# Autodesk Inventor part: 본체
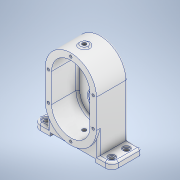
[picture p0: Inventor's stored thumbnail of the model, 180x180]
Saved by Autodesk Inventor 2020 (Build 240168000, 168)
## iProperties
Created: 2021-05
Part Number: 본체
Material: 알루미늄 6061
Document SubType Name: Modeling
Designer: Owner
Density: 2.7 g/cm^3
Appearance: 알루미늄 - 평지
Mass: 752.167 g
Surface Area: 589.363 cm^2
Volume: 278.58 cm^3
Author: Owner
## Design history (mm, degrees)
sketch "스케치2"
  geometry: L1 (0, 17.5)-(0, -17.5); L2 (40, -22.5)-(40, 22.5); L3 (-40, 22.5)-(-40, -22.5); A1 r 40 centre (0, -22.5) between (-40, -22.5) and (40, -22.5); A2 r 40 centre (0, 22.5) between (40, 22.5) and (-40, 22.5); 2 further points
  constraints: 8 end point, 6 point on circle, 4 tangent, 2 centre point, 2 point on line, 1 coincident, 1 midpoint, 1 parallel, 1 vertical
  dimensions: "d7" = 80 diameter of A2; "d48" = 45 distance of A1.centre A2.centre
extrude "돌출1" new body sketch "스케치2" distance "d8" = 49; taper "d9" = 0 deg
sketch "스케치3"
  geometry: L1 (-40, 22.5)-(-40, -22.5) reference; L2 (-40, 22.5)-(-40, -22.5) reference; L3 (40, -22.5)-(40, 22.5) reference; L4 (0, 7.5)-(0, -7.5); L5 (30, -22.5)-(30, 22.5); L6 (-30, 22.5)-(-30, -22.5); A1 r 40 centre (0, 22.5) between (40, 22.5) and (-40, 22.5) reference; A2 r 40 centre (0, -22.5) between (-40, -22.5) and (40, -22.5) reference; A3 r 40 centre (0, 22.5) between (40, 22.5) and (-40, 22.5) reference; A4 r 30 centre (0, -22.5) between (-30, -22.5) and (30, -22.5); A5 r 30 centre (0, 22.5) between (30, 22.5) and (-30, 22.5); 2 further points
  constraints: 8 end point, 6 point on circle, 4 tangent, 2 centre point, 2 point on line, 1 coincident, 1 midpoint, 1 parallel, 1 vertical
  dimensions: "d11" = 60 diameter of A5; "d47" = 45 distance of A4.centre A5.centre
extrude "돌출2" cut sketch "스케치3" distance "d12" = 41; taper "d13" = 0 deg
sketch "스케치4"
  geometry: L1 (0, -22.5)-(0, -69.5); L2 (-61, -69.5)-(-61, -59.5); L3 (-61, -59.5)-(-40, -59.5); L4 (-40, -59.5)-(-40, -22.5); L5 (40, -59.5)-(40, -22.5); L6 (61, -59.5)-(40, -59.5); L7 (61, -69.5)-(61, -59.5); L8 (-35, -69.5)-(35, -69.5); L9 (-61, -69.5)-(-35, -69.5); L10 (61, -69.5)-(35, -69.5); L11 (-35, -69.5)-(-35, -64.5); L12 (-35, -64.5)-(35, -64.5); L13 (35, -69.5)-(35, -64.5); A1 r 40 centre (0, -22.5) between (-40, -22.5) and (40, -22.5) reference; 1 further point
  constraints: 26 end point, 3 perpendicular, 3 vertical, 2 symmetric about line, 1 collinear, 1 horizontal, 1 midpoint
  dimensions: "d14" = 47 distance of L1.end L1.start; "d15" = 122 distance of L2.start L7.start; "d16" = 10 distance of L2.start L2.end; "d17" = 21 distance of L2.end L3.end; "d18" = 70 distance of L8.start L8.end; "d19" = 5 distance of L8.start L11.end
extrude "돌출3" join sketch "스케치4" distance "d20" = 49; taper "d21" = 0 deg
sketch "스케치5"
  geometry: L1 (0, 22.5)-(0, -22.5); C1 r 14 at (0, -22.5); C2 r 14 at (0, 22.5); 2 further points
  constraints: 3 coincident, 2 centre point, 2 end point, 1 midpoint, 1 point on line, 1 vertical
  dimensions: "d22" = 45 distance of L1.start L1.end; "d24" = 28 diameter of C1; "d25" = 28 diameter of C2
extrude "돌출4" cut sketch "스케치5" distance "d26" = 8; taper "d27" = 0 deg
sketch "스케치6"
  geometry: L1 (0, 48.5)-(0, -48.5); L2 (-26, 22.5)-(-26, -22.5); L3 (26, -22.5)-(26, 22.5); A1 r 26 centre (0, 22.5) between (26, 22.5) and (-26, 22.5); A2 r 26 centre (0, -22.5) between (-26, -22.5) and (26, -22.5); 2 further points
  constraints: 8 end point, 6 point on circle, 4 tangent, 2 centre point, 2 point on line, 1 coincident, 1 midpoint, 1 parallel, 1 vertical
  dimensions: "d28" = 52 distance between parallel lines of L2 L3; "d29" = 45 distance of A2.centre A1.centre
extrude "돌출5" join sketch "스케치6" distance "d30" = 8; taper "d31" = 0 deg
sketch "스케치7"
  geometry: L1 (0, 0)-(0, -45); C1 r 11 at (0, 0); C2 r 10 at (0, -45); 2 further points
  constraints: 3 coincident, 2 centre point, 2 end point, 1 midpoint, 1 vertical
  dimensions: "d35" = 45 distance of L1.start L1.end; "d36" = 22 diameter of C1; "d37" = 20 diameter of C2
extrude "돌출6" cut sketch "스케치7" distance "d38" = 4; taper "d39" = 0 deg
sketch "스케치8"
  geometry: L1 (0, 0)-(0, -45); C1 r 14 at (0, 0); 2 further points
  constraints: 2 coincident, 2 end point, 1 centre point, 1 midpoint, 1 vertical
  dimensions: "d40" = 45 distance of L1.start L1.end; "d41" = 28 diameter of C1
extrude "돌출7" cut sketch "스케치8" extent not by distance; stored distance "d42" = 3; taper "d43" = 0 deg
sketch "스케치9"
  geometry: L1 (-35, 22.5)-(-35, -22.5); L2 (35, 22.5)-(35, -22.5); L3 (0, 22.5)-(0, 12.5); L4 (0, -12.5)-(0, -22.5); A1 r 35 centre (0, 22.5) between (35, 22.5) and (-35, 22.5); A2 r 35 centre (0, -22.5) between (-35, -22.5) and (35, -22.5); 8 further points
  constraints: 8 end point, 8 point on circle, 7 coincident, 2 centre point, 2 vertical, 1 tangent
  dimensions: "d44" = 45 distance of L3.start L4.end
hole "구멍1" sketch "스케치9" at (0, 57.5), (-35, 22.5), (35, 22.5), (0, -57.5), (-35, -22.5), (35, -22.5) diameter "d49" = 4; stored, may be unused: countersink angle "d53" = 90 deg, drill point angle "d55" = 118 deg; dims "d50" = 6, "d51" = 4, "d52" = 2, "d54" = 10
sketch "스케치11" dims "d59" = 40
  geometry: L1 (0, 22.5)-(0, -7.5); L2 (0, -7.5)-(-26, -7.5); L3 (0, -7.5)-(26, -7.5); L4 (-26, 22.5)-(-26, -22.5) reference; L5 (26, -22.5)-(26, 22.5) reference; A1 r 26 centre (0, -22.5) between (-26, -22.5) and (26, -22.5) reference; 6 further points
  constraints: 6 end point, 2 coincident, 2 horizontal, 1 vertical alignment, 6 other
  dimensions: "d58" = 30 distance of L1.start L1.end; "d62" = 360 deg dimension on L1.start point (0, 42.5) (derived)
hole "구멍2" sketch "스케치11" diameter "d64" = 4; stored, may be unused: countersink angle "d68" = 90 deg, drill point angle "d70" = 118 deg; dims "d65" = 6, "d66" = 4, "d67" = 2, "d69" = 10
extrude "돌출8" join sketch "스케치11" distance "d71" = 3; taper "d72" = 0 deg
sketch "스케치12"
  geometry: 1 further point
node "작업 평면3"
sketch "스케치13"
  geometry: L1 (0, -22.5)-(0, -69.5); L2 (-61, -69.5)-(-61, -59.5); L3 (-61, -59.5)-(-40, -59.5); L4 (-40, -59.5)-(-40, -22.5); L5 (40, -59.5)-(40, -22.5); L6 (61, -59.5)-(40, -59.5); L7 (61, -69.5)-(61, -59.5); L8 (-35, -69.5)-(35, -69.5); L9 (-61, -69.5)-(-35, -69.5); L10 (61, -69.5)-(35, -69.5); L11 (-35, -69.5)-(-35, -64.5); L12 (-35, -64.5)-(35, -64.5); L13 (35, -69.5)-(35, -64.5); A1 r 40 centre (0, -22.5) between (-40, -22.5) and (40, -22.5); 2 further points
  constraints: 26 end point, 3 perpendicular, 3 vertical, 2 point on circle, 2 symmetric about line, 1 centre point, 1 collinear, 1 horizontal, 1 midpoint
  dimensions: "d74" = 47 distance of L1.end L1.start; "d75" = 122 distance of L2.start L7.start; "d76" = 10 distance of L2.start L2.end; "d77" = 21 distance of L2.end L3.end; "d78" = 70 distance of L8.start L8.end; "d79" = 5 distance of L8.start L11.end
extrude "돌출9" cut sketch "스케치13" distance "d80" = 49; taper "d81" = 0 deg
node "작업 평면4"
sketch "스케치15"
  geometry: 1 further point
fillet "모깎기1" dims "d91" = 10
sketch "스케치17"
  geometry: C1 r 5.5 at (-11, 33); C2 r 5.5 at (-11, 10); C3 r 5.5 at (91, 33); C4 r 5.5 at (91, 10); C5 r 3.3 at (91, 33); C6 r 3.3 at (91, 10); C7 r 3.3 at (-11, 33); C8 r 3.3 at (-11, 10); A1 r 10 centre (-11, 10) between (-21, 10) and (-11, 0) reference; A2 r 10 centre (-11, 33) between (-11, 43) and (-21, 33) reference; A3 r 10 centre (91, 33) between (101, 33) and (91, 43) reference; A4 r 10 centre (91, 10) between (91, 0) and (101, 10) reference; 5 further points
  constraints: 12 coincident, 8 centre point
  dimensions: "d92" = 11 diameter of C1; "d93" = 11 diameter of C2; "d94" = 11 diameter of C3; "d95" = 11 diameter of C4; "d96" = 6.6 diameter of C5; "d97" = 6.6 diameter of C6; "d98" = 6.6 diameter of C7; "d99" = 6.6 diameter of C8
extrude "돌출11" cut sketch "스케치17" distance "d100" = 2; taper "d101" = 0 deg
extrude "돌출12" cut sketch "스케치17" extent not by distance; stored distance "d102" = 0; taper "d103" = 0 deg
node "작업 평면5"
sketch "스케치18"
  geometry: L1 (-30, 49)-(30, 49) reference; L2 (0, 49)-(0, 28); C1 r 6 at (0, 28); 1 further point
  constraints: 2 end point, 1 centre point, 1 coincident, 1 midpoint
  dimensions: "d105" = 21 distance of L2.start L2.end; "d106" = 12 diameter of C1
extrude "돌출13" join sketch "스케치18" stored distance "d107" = 3; taper "d108" = 0 deg
sketch "스케치19"
  geometry: C1 r 6 at (0, 0) reference; 2 further points
  constraints: 1 coincident
hole "구멍3" sketch "스케치19" at (0, 0) diameter "d109" = 6; stored, may be unused: countersink angle "d113" = 90 deg, drill point angle "d115" = 118 deg; dims "d110" = 6, "d111" = 4, "d112" = 2, "d114" = 6
sketch "스케치21"
  geometry: C1 r 3 at (35, -18) reference; C2 r 3 at (35, -18) reference; C3 r 6 at (35, -18); 1 further point
  constraints: 1 centre point, 1 coincident
  dimensions: "d119" = 12 diameter of C3
extrude "돌출14" cut sketch "스케치21" distance "d120" = 1; taper "d121" = 0 deg
fillet "모깎기2" dims "d122" = 0.3
fillet "모깎기3" dims "d123" = 3
chamfer "모따기1" distance "d124" = 1; stored, may be unused: second distance "d125" = 2, angle "d126" = 45 deg
fillet "모깎기4" dims "d127" = 3
fillet "모깎기5" dims "d128" = 3
sketch "스케치22"
  geometry: L1 (-58, -69.5)-(-35, -69.5) reference; L2 (0, -69.5)-(0, -57.5); L3 (59, -30)-(109, -30); L4 (0, -57.5)-(30, -57.5); L5 (0, -57.5)-(-30, -57.5); L6 (30, -59.5)-(0, -59.5); L7 (0, -59.5)-(-30, -59.5); L8 (-30, -59.5)-(30, -59.5); C1 r 2 at (0, -57.5) reference; 1 further point
  constraints: 14 end point, 4 horizontal, 1 collinear, 1 other
  dimensions: "d130" = 50 distance of L3.start L3.end; "d134" = 2 distance between parallel lines of L4 L6
extrude "돌출15" join sketch "스케치22" distance "d135" = 0.5; taper "d136" = 0 deg
feature "스레드1" dims "d137" = 8, "d138" = 0
feature "스레드2" dims "d139" = 8, "d140" = 0
feature "스레드3" dims "d141" = 8, "d142" = 0
feature "스레드4" dims "d143" = 8, "d144" = 0
feature "스레드5" dims "d145" = 8, "d146" = 0
feature "스레드6" dims "d147" = 8, "d148" = 0
feature "스레드7" dims "d149" = 8, "d150" = 0
feature "스레드8" dims "d151" = 8, "d152" = 0
feature "스레드9" dims "d153" = 8, "d154" = 0
feature "스레드10" dims "d155" = 11.15, "d156" = 0
feature "스레드11" dims "d157" = 11.65, "d158" = 0
node "솔리드1"
node "투영된 루프1"
feature "A9D066F2-1C7D-4E18-AEED-F7BC21143FA4" dims "d139" = 8, "d140" = 0
other parameters: "d82" = -3, "d104" = 62.5
